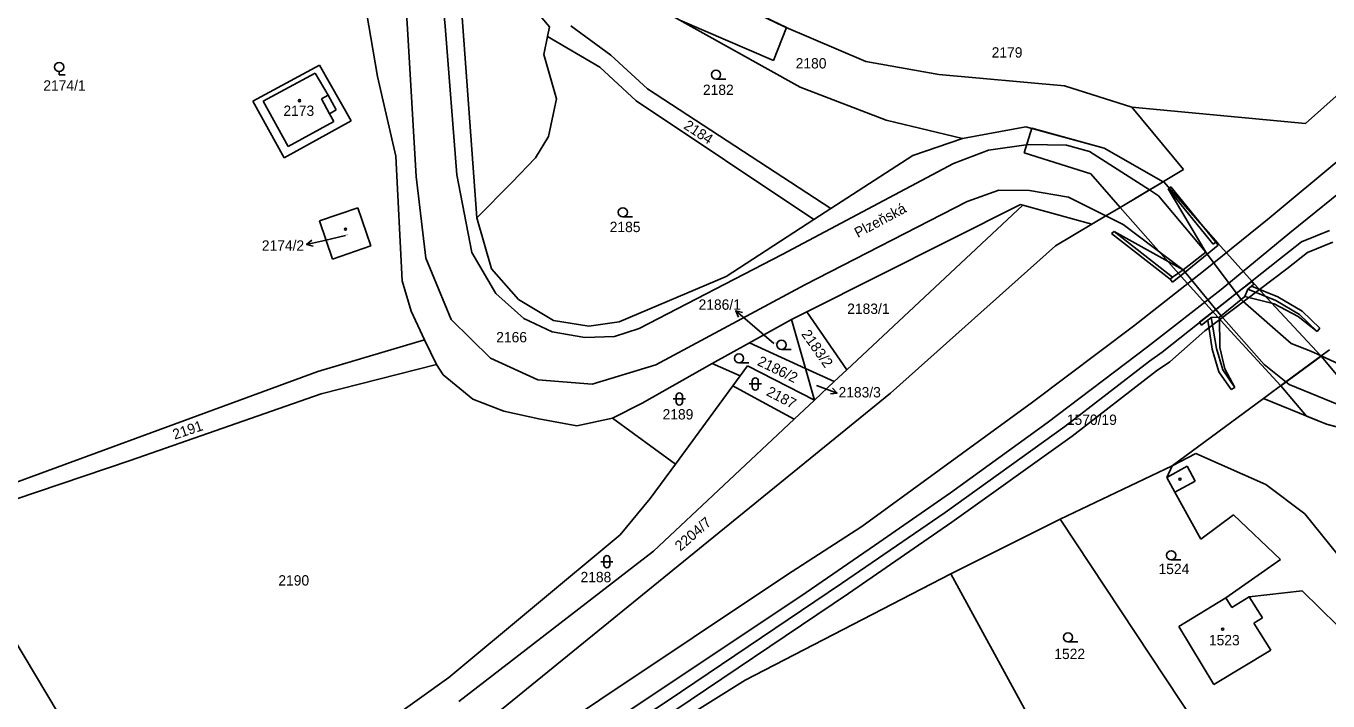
# Model space of a CAD drawing. Extents: x -785744 to -782822, y -1067550 to -1063910.
# Drawn here: x -784600.3 to -784386.3, y -1065287.5 to -1065176.5 of the extents above; entities that cross this region are included whole.
import ezdxf

# ---------------------------------------------------------------- set-up
doc = ezdxf.new("R2010")
doc.units = 0
for name, color, linetype in [('Hranice parcel', 7, 'Continuous'), ('Parcelní čísla', 7, 'Continuous'), ('Pop_ČP_popisy', 7, 'Continuous'), ('Poz_předměty', 7, 'Continuous'), ('Vnitřní kresba', 7, 'Continuous'), ('Věcná břemena k části', 7, 'Continuous'), ('Značky budov', 7, 'Continuous'), ('Značky kultur', 7, 'Continuous')]:
    doc.layers.add(name, color=color, linetype=linetype)

msp = doc.modelspace()

# ---------------------------------------------------------------- linework, layer by layer
at = {"layer": 'Hranice parcel'}
for p, q in [((-784552.06, -1065182.97), (-784563, -1065188.88)), ((-784546.86, -1065192.13), (-784552.06, -1065182.97)), ((-784563, -1065188.88), (-784557.87, -1065198.2)), ((-784557.87, -1065198.2), (-784546.86, -1065192.13)), ((-784545.77, -1065206.43), (-784552.05, -1065208.57)), ((-784543.63, -1065212.67), (-784545.77, -1065206.43)), ((-784552.05, -1065208.57), (-784549.89, -1065214.83)), ((-784549.89, -1065214.83), (-784543.63, -1065212.67))]:
    msp.add_line(p, q, dxfattribs=at)
for points in [[(-784517.54, -1065161.79), (-784473.06, -1065186.61)], [(-784545.73, -1065165.86), (-784542.54, -1065184.81)], [(-784520.15, -1065169.65), (-784514.28, -1065176.7)], [(-784492.27, -1065168.61), (-784475.72, -1065176.6)], [(-784510.74, -1065176.52), (-784504.17, -1065181.33)], [(-784515.21, -1065181.22), (-784514.6, -1065178.27)], [(-784514.6, -1065178.27), (-784514.28, -1065176.7)], [(-784514.6, -1065178.27), (-784506, -1065183.32)], [(-784475.72, -1065176.6), (-784462.28, -1065182.38)], [(-784515.21, -1065181.22), (-784513.12, -1065188.5)], [(-784504.17, -1065181.33), (-784498.16, -1065186.85)], [(-784462.28, -1065182.38), (-784450.3, -1065184.53)], [(-784542.54, -1065184.81), (-784539.51, -1065197.92)], [(-784506, -1065183.32), (-784499.99, -1065188.84)], [(-784450.3, -1065184.53), (-784429.65, -1065186.38)], [(-784498.16, -1065186.85), (-784468.03, -1065206.54)], [(-784473.06, -1065186.61), (-784458.92, -1065192.03)], [(-784429.65, -1065186.38), (-784418.55, -1065189.89)], [(-784390.01, -1065192.56), (-784383.97, -1065187.19)], [(-784514.41, -1065194.7), (-784513.12, -1065188.5)], [(-784499.99, -1065188.84), (-784470.84, -1065208.36)], [(-784418.55, -1065189.89), (-784410.06, -1065200.14)], [(-784418.55, -1065189.89), (-784390.01, -1065192.56)], [(-784458.92, -1065192.03), (-784446.37, -1065195.03)], [(-784446.37, -1065195.03), (-784435.96, -1065193.09)], [(-784435.96, -1065193.09), (-784423.08, -1065196.59)], [(-784516.55, -1065198.18), (-784514.41, -1065194.7)], [(-784454.53, -1065197.8), (-784446.37, -1065195.03)], [(-784539.51, -1065197.92), (-784538.44, -1065218.41)], [(-784468.03, -1065206.54), (-784454.53, -1065197.8)], [(-784423.08, -1065196.59), (-784413.42, -1065202.14)], [(-784520.45, -1065202.26), (-784516.55, -1065198.18)], [(-784415.68, -1065203.48), (-784413.42, -1065202.14)], [(-784413.42, -1065202.14), (-784413.38, -1065202.11)], [(-784413.38, -1065202.11), (-784410.06, -1065200.14)], [(-784526.22, -1065208.06), (-784520.45, -1065202.26)], [(-784420.49, -1065206.34), (-784415.68, -1065203.48)], [(-784471.95, -1065223.51), (-784436.83, -1065205.89)], [(-784465.39, -1065233.05), (-784436.49, -1065205.98)], [(-784436.83, -1065205.89), (-784436.49, -1065205.98)], [(-784436.49, -1065205.98), (-784425.12, -1065209.1)], [(-784422.82, -1065207.73), (-784420.49, -1065206.34)], [(-784526.22, -1065208.06), (-784523.8, -1065216.46)], [(-784485.24, -1065217.69), (-784470.84, -1065208.36)], [(-784470.84, -1065208.36), (-784468.03, -1065206.54)], [(-784425.12, -1065209.1), (-784422.82, -1065207.73)], [(-784431.08, -1065212.65), (-784425.12, -1065209.1)], [(-784458.2, -1065236.9), (-784431.08, -1065212.65)], [(-784523.8, -1065216.46), (-784519.37, -1065221.48)], [(-784538.44, -1065218.41), (-784536.98, -1065223.41)], [(-784502.79, -1065225.13), (-784485.24, -1065217.69)], [(-784536.98, -1065223.41), (-784534.8, -1065228.11)], [(-784519.37, -1065221.48), (-784513.59, -1065224.91)], [(-784474.49, -1065224.79), (-784471.95, -1065223.51)], [(-784471.95, -1065223.51), (-784465.39, -1065233.05)], [(-784513.59, -1065224.91), (-784507.78, -1065225.89)], [(-784507.78, -1065225.89), (-784502.79, -1065225.13)], [(-784481.4, -1065228.62), (-784474.49, -1065224.79)], [(-784474.49, -1065224.79), (-784472.21, -1065232.81)], [(-784552.32, -1065233.33), (-784534.8, -1065228.11)], [(-784534.8, -1065228.11), (-784532.8, -1065232.17)], [(-784487.53, -1065232.02), (-784481.4, -1065228.62)], [(-784472.21, -1065232.81), (-784481.4, -1065228.62)], [(-784387.44, -1065230.75), (-784386.09, -1065229.75)], [(-784499, -1065238.52), (-784487.53, -1065232.02)], [(-784487.53, -1065232.02), (-784482.91, -1065234.02)], [(-784393.23, -1065235.02), (-784387.44, -1065230.75)], [(-784614.97, -1065256.3), (-784552.32, -1065233.33)], [(-784551.79, -1065236.97), (-784532.8, -1065232.17)], [(-784532.8, -1065232.17), (-784531.75, -1065233.84)], [(-784531.75, -1065233.84), (-784526.84, -1065237.85)], [(-784484.13, -1065235.68), (-784482.91, -1065234.02)], [(-784482.91, -1065234.02), (-784481.73, -1065232.41)], [(-784481.73, -1065232.41), (-784470.72, -1065238.04)], [(-784472.21, -1065232.81), (-784470.72, -1065238.04)], [(-784467.46, -1065234.98), (-784472.21, -1065232.81)], [(-784467.46, -1065234.98), (-784465.39, -1065233.05)], [(-784493.56, -1065248.53), (-784484.13, -1065235.68)], [(-784484.13, -1065235.68), (-784480.61, -1065237.59)], [(-784470.72, -1065238.04), (-784467.46, -1065234.98)], [(-784396.95, -1065237.76), (-784393.23, -1065235.02)], [(-784583.17, -1065247.96), (-784551.79, -1065236.97)], [(-784526.84, -1065237.85), (-784521.76, -1065239.84)], [(-784525.39, -1065291.49), (-784458.2, -1065236.9)], [(-784503.89, -1065241), (-784499, -1065238.52)], [(-784480.61, -1065237.59), (-784474.03, -1065241.14)], [(-784474.03, -1065241.14), (-784470.72, -1065238.04)], [(-784411.93, -1065248.8), (-784396.95, -1065237.76)], [(-784396.95, -1065237.76), (-784386.57, -1065241.98)], [(-784521.76, -1065239.84), (-784516, -1065241.1)], [(-784516, -1065241.1), (-784509.76, -1065242.25)], [(-784509.76, -1065242.25), (-784503.89, -1065241)], [(-784503.89, -1065241), (-784493.56, -1065248.53)], [(-784497.16, -1065262.83), (-784474.03, -1065241.14)], [(-784386.57, -1065241.98), (-784367.8, -1065246.94)], [(-784411.93, -1065248.8), (-784408.06, -1065246.78)], [(-784408.06, -1065246.78), (-784396.56, -1065251.91)], [(-784613.69, -1065258.26), (-784583.17, -1065247.96)], [(-784497.71, -1065254.17), (-784493.56, -1065248.53)], [(-784430.33, -1065257.59), (-784411.93, -1065248.8)], [(-784412.83, -1065250.73), (-784411.93, -1065248.8)], [(-784412.83, -1065250.73), (-784411.52, -1065253.12)], [(-784411.52, -1065253.12), (-784407.2, -1065260.87)], [(-784396.56, -1065251.91), (-784390.15, -1065256.71)], [(-784502.63, -1065260.13), (-784497.71, -1065254.17)], [(-784448.28, -1065266.55), (-784430.33, -1065257.59)], [(-784430.33, -1065257.59), (-784400.65, -1065302.45)], [(-784407.2, -1065260.87), (-784401.84, -1065256.88)], [(-784401.84, -1065256.88), (-784394.13, -1065264.23)], [(-784390.15, -1065256.71), (-784374.84, -1065275.66)], [(-784613.69, -1065258.26), (-784578.25, -1065317.58)], [(-784530.8, -1065283.58), (-784502.63, -1065260.13)], [(-784529.14, -1065287.53), (-784497.16, -1065262.83)], [(-784403.13, -1065270.49), (-784394.13, -1065264.23)], [(-784482.12, -1065284.05), (-784448.28, -1065266.55)], [(-784448.28, -1065266.55), (-784435.56, -1065289.93)], [(-784410.85, -1065275.23), (-784403.13, -1065270.49)], [(-784399.28, -1065270.36), (-784390.58, -1065269.36)], [(-784399.28, -1065270.36), (-784397.09, -1065273.81)], [(-784390.58, -1065269.36), (-784381.87, -1065277.9)], [(-784398.49, -1065274.69), (-784397.09, -1065273.81)], [(-784398.49, -1065274.69), (-784395.71, -1065279.1)], [(-784410.85, -1065275.23), (-784405.08, -1065284.77)], [(-784405.08, -1065284.77), (-784395.71, -1065279.1)], [(-784578.25, -1065317.58), (-784530.8, -1065283.58)], [(-784520.38, -1065307.98), (-784482.12, -1065284.05)]]:
    msp.add_lwpolyline(points, dxfattribs=at)
at = {"layer": 'Pop_ČP_popisy'}
for p, q in [((-784551.24, -1065211.76), (-784554.16, -1065212.45)), ((-784481.36, -1065225.3), (-784483.64, -1065223.35)), ((-784469.8, -1065235.83), (-784466.99, -1065236.87))]:
    msp.add_line(p, q, dxfattribs=at)
for points in [[(-784553.07, -1065212.7), (-784554.16, -1065212.45), (-784553.3, -1065211.73)], [(-784547.79, -1065210.95), (-784551.24, -1065211.76)], [(-784483.21, -1065224.38), (-784483.64, -1065223.35), (-784482.56, -1065223.62)], [(-784477.39, -1065228.7), (-784481.36, -1065225.3)], [(-784470.36, -1065235.62), (-784469.8, -1065235.83)], [(-784467.75, -1065236.06), (-784466.99, -1065236.87), (-784468.1, -1065236.99)]]:
    msp.add_lwpolyline(points, dxfattribs=at)
at = {"layer": 'Poz_předměty'}
for points in [[(-784384.2, -1065198.29), (-784395.97, -1065208.11)], [(-784381.48, -1065201.54), (-784392.6, -1065210.55)], [(-784395.97, -1065208.11), (-784406.77, -1065216.83)], [(-784392.6, -1065210.55), (-784403.9, -1065219.84)], [(-784406.77, -1065216.83), (-784418.29, -1065225.85)], [(-784403.9, -1065219.84), (-784415.98, -1065229.26)], [(-784418.29, -1065225.85), (-784434.91, -1065238.36)], [(-784415.98, -1065229.26), (-784432.49, -1065241.75)], [(-784434.91, -1065238.36), (-784450.21, -1065249.51)], [(-784432.49, -1065241.75), (-784448.38, -1065253.26)], [(-784450.21, -1065249.51), (-784462.94, -1065258.78)], [(-784460.87, -1065261.89), (-784448.38, -1065253.26)], [(-784462.94, -1065258.78), (-784475.29, -1065266.76)], [(-784472.93, -1065270.24), (-784460.87, -1065261.89)], [(-784475.29, -1065266.76), (-784521.3, -1065297.53)], [(-784519.05, -1065300.99), (-784472.93, -1065270.24)]]:
    msp.add_lwpolyline(points, dxfattribs=at)
at = {"layer": 'Vnitřní kresba'}
for p, q in [((-784552.78, -1065184.27), (-784561.33, -1065188.88)), ((-784550.64, -1065187.89), (-784552.78, -1065184.27)), ((-784561.33, -1065188.88), (-784557.22, -1065196.35)), ((-784550.64, -1065187.89), (-784551.74, -1065188.5)), ((-784551.74, -1065188.5), (-784550.4, -1065190.95)), ((-784549.29, -1065190.34), (-784550.64, -1065187.89)), ((-784550.4, -1065190.95), (-784549.29, -1065190.34)), ((-784549.7, -1065192.21), (-784550.4, -1065190.95)), ((-784557.22, -1065196.35), (-784549.7, -1065192.21))]:
    msp.add_line(p, q, dxfattribs=at)
for points in [[(-784539.74, -1065143.76), (-784537.59, -1065177.01)], [(-784534.44, -1065143.88), (-784531.38, -1065176.57)], [(-784530.14, -1065154.09), (-784526.22, -1065208.06)], [(-784537.59, -1065177.01), (-784536.17, -1065201.27)], [(-784531.38, -1065176.57), (-784529.48, -1065200.98)], [(-784447.86, -1065199.13), (-784442.14, -1065196.92)], [(-784442.14, -1065196.92), (-784435.53, -1065195.99)], [(-784435.53, -1065195.99), (-784429.3, -1065196.1)], [(-784429.3, -1065196.1), (-784425.54, -1065197.18)], [(-784425.54, -1065197.18), (-784415.68, -1065203.48)], [(-784476.02, -1065214.1), (-784447.86, -1065199.13)], [(-784536.17, -1065201.27), (-784534.59, -1065214.69)], [(-784529.48, -1065200.98), (-784527.02, -1065213.75)], [(-784445.6, -1065205.36), (-784440.41, -1065203.5)], [(-784440.41, -1065203.5), (-784435.39, -1065203.58)], [(-784435.39, -1065203.58), (-784428.98, -1065204.65)], [(-784415.68, -1065203.48), (-784414.2, -1065204.43)], [(-784412.61, -1065203.3), (-784412.17, -1065202.95)], [(-784412.61, -1065203.3), (-784406.42, -1065213.7)], [(-784412.61, -1065203.3), (-784405.17, -1065212.4)], [(-784412.17, -1065202.95), (-784404.75, -1065212.06)], [(-784472.3, -1065219.07), (-784445.6, -1065205.36)], [(-784428.98, -1065204.65), (-784422.82, -1065207.73)], [(-784414.2, -1065204.43), (-784406.42, -1065213.7)], [(-784422.82, -1065207.73), (-784419.99, -1065209.15)], [(-784421.92, -1065210.65), (-784421.49, -1065210.31)], [(-784421.92, -1065210.65), (-784412.28, -1065218.16)], [(-784421.49, -1065210.31), (-784411.85, -1065217.82)], [(-784421.49, -1065210.31), (-784410.12, -1065216.6)], [(-784419.99, -1065209.15), (-784410.12, -1065216.6)], [(-784406.18, -1065214.02), (-784404.36, -1065212.55)], [(-784405.17, -1065212.4), (-784404.75, -1065212.06)], [(-784404.75, -1065212.06), (-784404.36, -1065212.55)], [(-784534.59, -1065214.69), (-784530.43, -1065224.75)], [(-784527.02, -1065213.75), (-784523.08, -1065220.5)], [(-784499.53, -1065226.26), (-784476.02, -1065214.1)], [(-784410.12, -1065216.6), (-784406.42, -1065213.7)], [(-784409.82, -1065216.97), (-784406.18, -1065214.02)], [(-784406.42, -1065213.7), (-784406.18, -1065214.02)], [(-784406.18, -1065214.02), (-784401.34, -1065220.44)], [(-784411.89, -1065218.65), (-784409.82, -1065216.97)], [(-784411.85, -1065217.82), (-784410.12, -1065216.6)], [(-784410.12, -1065216.6), (-784409.82, -1065216.97)], [(-784409.82, -1065216.97), (-784404.76, -1065223.11)], [(-784496.78, -1065232.22), (-784472.3, -1065219.07)], [(-784412.28, -1065218.16), (-784411.85, -1065217.82)], [(-784412.28, -1065218.16), (-784411.89, -1065218.65)], [(-784401.34, -1065220.44), (-784398.86, -1065218.5)], [(-784399.51, -1065219.77), (-784398.92, -1065219.31)], [(-784398.92, -1065219.31), (-784398.49, -1065218.97)], [(-784398.92, -1065219.31), (-784394.55, -1065221.03)], [(-784398.86, -1065218.5), (-784398.49, -1065218.97)], [(-784523.08, -1065220.5), (-784518.47, -1065224.58)], [(-784404.76, -1065223.11), (-784401.34, -1065220.44)], [(-784401.34, -1065220.44), (-784400.57, -1065221.46)], [(-784400.57, -1065221.46), (-784400.01, -1065221)], [(-784400.01, -1065221), (-784399.51, -1065219.77)], [(-784400.01, -1065221), (-784395.17, -1065222.18)], [(-784399.51, -1065219.77), (-784394.88, -1065221.65)], [(-784394.55, -1065221.03), (-784390.55, -1065223.4)], [(-784407.46, -1065225.22), (-784404.76, -1065223.11)], [(-784404.76, -1065223.11), (-784403.88, -1065224.19)], [(-784403.88, -1065224.19), (-784400.57, -1065221.46)], [(-784400.57, -1065221.46), (-784400.33, -1065221.77)], [(-784400.33, -1065221.77), (-784392.35, -1065228.69)], [(-784395.17, -1065222.18), (-784391.24, -1065224.27)], [(-784394.88, -1065221.65), (-784390.99, -1065223.95)], [(-784390.55, -1065223.4), (-784387.65, -1065226.2)], [(-784530.43, -1065224.75), (-784523.97, -1065231.13)], [(-784518.47, -1065224.58), (-784513.84, -1065226.8)], [(-784407.46, -1065225.22), (-784407.09, -1065225.69)], [(-784407.09, -1065225.69), (-784406.06, -1065224.89)], [(-784406.06, -1065224.89), (-784405.51, -1065224.46)], [(-784406.06, -1065224.89), (-784405.34, -1065229.67)], [(-784405.51, -1065224.46), (-784404.13, -1065224.4)], [(-784405.51, -1065224.46), (-784404.66, -1065229.51)], [(-784404.13, -1065224.4), (-784403.88, -1065224.19)], [(-784404.13, -1065224.4), (-784404.08, -1065229.38)], [(-784403.88, -1065224.19), (-784396.83, -1065232.18)], [(-784391.24, -1065224.27), (-784388.09, -1065226.75)], [(-784390.99, -1065223.95), (-784388.09, -1065226.75)], [(-784513.84, -1065226.8), (-784508.45, -1065227.7)], [(-784508.45, -1065227.7), (-784503.55, -1065227.55)], [(-784503.55, -1065227.55), (-784499.53, -1065226.26)], [(-784388.09, -1065226.75), (-784387.65, -1065226.2)], [(-784405.34, -1065229.67), (-784404.25, -1065233.37)], [(-784404.66, -1065229.51), (-784403.63, -1065233.04)], [(-784404.08, -1065229.38), (-784403.28, -1065232.86)], [(-784392.35, -1065228.69), (-784389.12, -1065229.97)], [(-784389.12, -1065229.97), (-784387.44, -1065230.75)], [(-784523.97, -1065231.13), (-784516.16, -1065234.69)], [(-784387.44, -1065230.75), (-784383.8, -1065232.43)], [(-784507.26, -1065235.4), (-784496.78, -1065232.22)], [(-784404.25, -1065233.37), (-784402.25, -1065236.27)], [(-784403.63, -1065233.04), (-784401.64, -1065235.95)], [(-784403.28, -1065232.86), (-784401.64, -1065235.95)], [(-784396.83, -1065232.18), (-784393.23, -1065235.02)], [(-784516.16, -1065234.69), (-784507.26, -1065235.4)], [(-784402.25, -1065236.27), (-784401.64, -1065235.95)], [(-784393.23, -1065235.02), (-784392.68, -1065235.46)], [(-784392.68, -1065235.46), (-784383.33, -1065239.27)], [(-784412.83, -1065250.73), (-784409.46, -1065248.89)], [(-784409.46, -1065248.89), (-784408.14, -1065251.33)], [(-784411.52, -1065253.12), (-784408.14, -1065251.33)], [(-784403.13, -1065270.49), (-784402.11, -1065272.12)], [(-784402.11, -1065272.12), (-784399.28, -1065270.36)]]:
    msp.add_lwpolyline(points, dxfattribs=at)
at = {"layer": 'Věcná břemena k části'}
for p, q in [((-784386.09, -1065210.14), (-784390.69, -1065212.01)), ((-784390.69, -1065212.01), (-784394.3, -1065214.85)), ((-784389.67, -1065213.75), (-784385.51, -1065212.06)), ((-784394.3, -1065214.85), (-784413.55, -1065230.15)), ((-784393.08, -1065216.43), (-784389.67, -1065213.75)), ((-784406.57, -1065226.63), (-784393.08, -1065216.43)), ((-784412.33, -1065231.73), (-784406.57, -1065226.63)), ((-784415.68, -1065231.59), (-784429.56, -1065242.34)), ((-784413.55, -1065230.15), (-784415.68, -1065231.59)), ((-784414.5, -1065233.21), (-784412.33, -1065231.73)), ((-784428.36, -1065243.94), (-784414.5, -1065233.21)), ((-784429.56, -1065242.34), (-784449.26, -1065256.46)), ((-784448.12, -1065258.1), (-784428.36, -1065243.94)), ((-784449.26, -1065256.46), (-784466.26, -1065268.15)), ((-784465.14, -1065269.81), (-784448.12, -1065258.1)), ((-784466.26, -1065268.15), (-784494.77, -1065287.38)), ((-784493.67, -1065289.04), (-784465.14, -1065269.81)), ((-784494.77, -1065287.38), (-784526.33, -1065307.97))]:
    msp.add_line(p, q, dxfattribs=at)
for points in [[(-784475.31, -1065176.78), (-784492.27, -1065168.61)], [(-784492.86, -1065175.56), (-784477.47, -1065182.2)], [(-784477.47, -1065182.2), (-784475.31, -1065176.78)], [(-784434.99, -1065193.35), (-784436.25, -1065197.38)], [(-784423.08, -1065196.59), (-784434.99, -1065193.35)], [(-784436.25, -1065197.38), (-784425.29, -1065200.82)], [(-784413.42, -1065202.14), (-784423.08, -1065196.59)], [(-784425.29, -1065200.82), (-784420.49, -1065206.34)], [(-784413.42, -1065202.14), (-784420.49, -1065206.34)], [(-784415.68, -1065203.48), (-784413.42, -1065202.14)], [(-784413.38, -1065202.11), (-784413.42, -1065202.14)], [(-784404.4, -1065212.25), (-784413.38, -1065202.11)], [(-784420.49, -1065206.34), (-784415.68, -1065203.48)], [(-784420.49, -1065206.34), (-784410.46, -1065217.69)], [(-784396.35, -1065221.19), (-784404.4, -1065212.25)], [(-784410.46, -1065217.69), (-784402.37, -1065226.69)], [(-784387.47, -1065230.78), (-784396.35, -1065221.19)], [(-784402.37, -1065226.69), (-784394.08, -1065235.65)], [(-784394.08, -1065235.65), (-784387.47, -1065230.78)], [(-784387.47, -1065230.78), (-784393.23, -1065235.02)], [(-784378.45, -1065241.52), (-784387.47, -1065230.78)], [(-784393.23, -1065235.02), (-784394.08, -1065235.65)], [(-784394.08, -1065235.65), (-784389.85, -1065240.64)], [(-784389.85, -1065240.64), (-784386.57, -1065241.98)], [(-784386.57, -1065241.98), (-784376.09, -1065244.75)]]:
    msp.add_lwpolyline(points, dxfattribs=at)
at = {"layer": 'Značky budov'}
for centre in [(-784555.34, -1065188.8), (-784547.79, -1065209.93), (-784410.65, -1065251.01), (-784403.63, -1065275.65)]:
    msp.add_circle(centre, 0.175, dxfattribs=at)
at = {"layer": 'Značky kultur'}
for p, q in [((-784486.88, -1065185.27), (-784485.28, -1065185.27)), ((-784502.2, -1065207.9), (-784500.6, -1065207.9)), ((-784476.13, -1065229.68), (-784474.53, -1065229.68)), ((-784483.1, -1065231.91), (-784481.5, -1065231.91)), ((-784481.44, -1065235.36), (-784479.44, -1065235.36)), ((-784480.94, -1065235.86), (-784480.94, -1065234.86)), ((-784479.94, -1065234.86), (-784479.94, -1065235.86)), ((-784493.92, -1065237.83), (-784491.92, -1065237.83)), ((-784493.42, -1065238.33), (-784493.42, -1065237.33)), ((-784492.42, -1065237.33), (-784492.42, -1065238.33)), ((-784505.33, -1065265.07), (-784505.33, -1065264.07)), ((-784504.33, -1065264.07), (-784504.33, -1065265.07)), ((-784505.83, -1065264.57), (-784503.83, -1065264.57)), ((-784412.09, -1065264.26), (-784410.49, -1065264.26)), ((-784429.04, -1065277.76), (-784427.44, -1065277.76))]:
    msp.add_line(p, q, dxfattribs=at)
msp.add_lwpolyline([(-784594.83, -1065184.04), (-784594.83, -1065184.54), (-784593.83, -1065184.54)], dxfattribs=at)
for centre in [(-784594.83, -1065183.29), (-784486.88, -1065184.52), (-784502.2, -1065207.15), (-784476.13, -1065228.93), (-784483.1, -1065231.16), (-784412.09, -1065263.51), (-784429.04, -1065277.01)]:
    msp.add_circle(centre, 0.75, dxfattribs=at)
for centre, start, end in [((-784480.44, -1065234.86), 0, 180), ((-784480.44, -1065235.86), 180, 0), ((-784492.92, -1065237.33), 0, 180), ((-784492.92, -1065238.33), 180, 0), ((-784504.83, -1065264.07), 0, 180), ((-784504.83, -1065265.07), 180, 0)]:
    msp.add_arc(centre, 0.5, start, end, dxfattribs=at)

# ---------------------------------------------------------------- texts
at = {"layer": 'Parcelní čísla'}
for s, height, p in [('2179', 1.7, (-784441.59, -1065181.73)), ('2180', 1.7, (-784473.8, -1065183.52)), ('2174/1', 1.7, (-784597.43, -1065187.16)), ('2182', 1.7, (-784489.04, -1065187.87)), ('2173', 1.7, (-784557.98, -1065191.31)), ('2185', 1.7, (-784504.36, -1065210.41)), ('2174/2', 0.1, (-784547.79, -1065210.95)), ('2183/1', 1.7, (-784465.33, -1065223.85)), ('2186/1', 0.1, (-784477.39, -1065228.7)), ('2183/3', 0.1, (-784470.36, -1065235.62)), ('2189', 1.7, (-784495.67, -1065241.2)), ('2188', 1.7, (-784509.16, -1065267.94)), ('1524', 1.7, (-784414.18, -1065266.61)), ('2190', 1.7, (-784558.81, -1065268.49)), ('1523', 1.7, (-784405.89, -1065278.31)), ('1522', 1.7, (-784431.3, -1065280.57))]:
    msp.add_text(s, height=height, dxfattribs=at).set_placement(p)
for s, rotation, p in [('2184', 326.7731, (-784492.34, -1065193.29)), ('2183/2', 305.2176, (-784472.95, -1065227.18)), ('2186/2', 333.9986, (-784480.24, -1065232.2)), ('2187', 332.4716, (-784478.76, -1065237.16)), ('2191', 18.5055, (-784575.85, -1065244.53))]:
    msp.add_text(s, height=1.7, rotation=rotation, dxfattribs=at).set_placement(p)
at = {"layer": 'Pop_ČP_popisy'}
for s, rotation, p in [('Plzeňská', 28.1711, (-784463.58, -1065211.4)), ('2204/7', 40.9033, (-784492.75, -1065262.93))]:
    msp.add_text(s, height=1.7, rotation=rotation, dxfattribs=at).set_placement(p)
for s, p in [('2174/2', (-784561.53, -1065213.46)), ('2186/1', (-784489.76, -1065223.17)), ('2166', (-784523.01, -1065228.52)), ('2183/3', (-784466.76, -1065237.58)), ('1570/19', (-784429.24, -1065242.09))]:
    msp.add_text(s, height=1.7, dxfattribs=at).set_placement(p)

doc.saveas('drawing.dxf')
